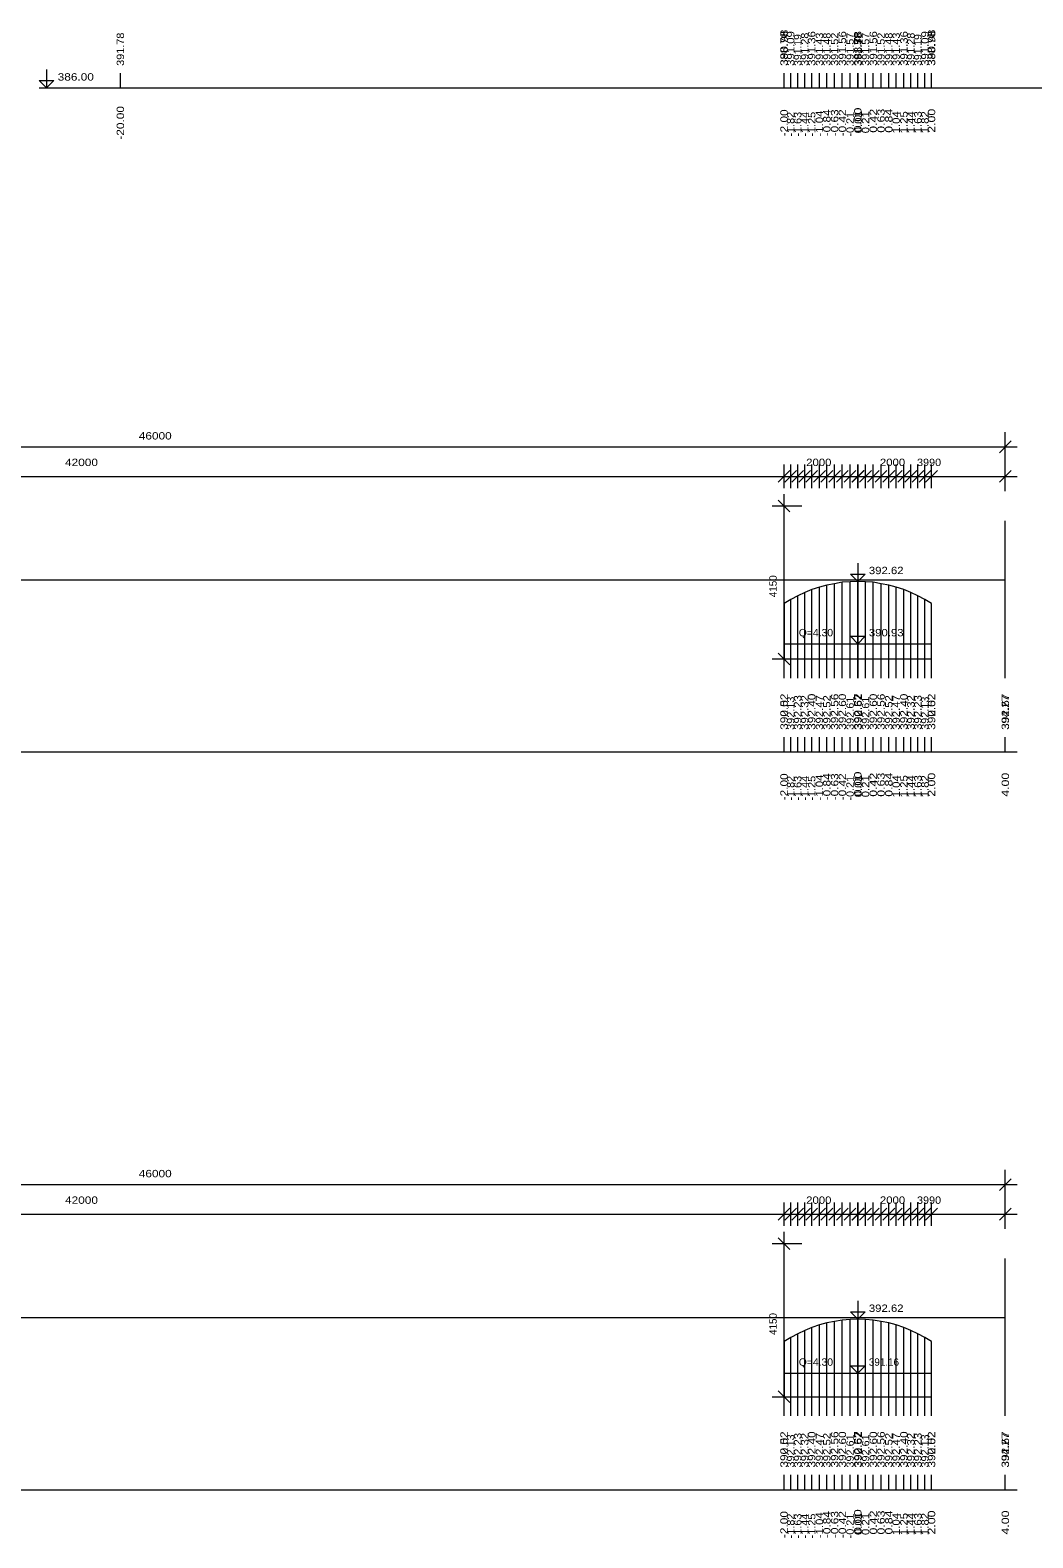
# Model space of a CAD drawing. Extents: x 7 to 442, y -393 to 441.
# Drawn here: x 399.59 to 426.79, y 354.66 to 395.53 of the extents above; entities that cross this region are included whole.
import ezdxf

# ---------------------------------------------------------------- set-up
doc = ezdxf.new("R2010")
doc.units = 0
doc.header["$LTSCALE"] = 0.08
doc.layers.add('7', color=7, linetype='Continuous', lineweight=13)

msp = doc.modelspace()

# ---------------------------------------------------------------- linework, layer by layer
at = {"layer": '7'}
for p, q in [((402.038, 393.966), (402.038, 394.366)), ((420.038, 393.966), (420.038, 394.366)), ((420.038, 393.966), (420.038, 394.366)), ((420.218, 393.966), (420.218, 394.366)), ((420.408, 393.966), (420.408, 394.366)), ((420.598, 393.966), (420.598, 394.366)), ((420.788, 393.966), (420.788, 394.366)), ((420.998, 393.966), (420.998, 394.366)), ((421.198, 393.966), (421.198, 394.366)), ((421.408, 393.966), (421.408, 394.366)), ((421.618, 393.966), (421.618, 394.366)), ((421.828, 393.966), (421.828, 394.366)), ((422.038, 393.966), (422.038, 394.366)), ((422.038, 393.966), (422.038, 394.366)), ((422.038, 393.966), (422.038, 394.366)), ((422.048, 393.966), (422.048, 394.366)), ((422.048, 393.966), (422.048, 394.366)), ((422.248, 393.966), (422.248, 394.366)), ((422.458, 393.966), (422.458, 394.366)), ((422.668, 393.966), (422.668, 394.366)), ((422.878, 393.966), (422.878, 394.366)), ((423.078, 393.966), (423.078, 394.366)), ((423.288, 393.966), (423.288, 394.366)), ((423.478, 393.966), (423.478, 394.366)), ((423.668, 393.966), (423.668, 394.366)), ((423.858, 393.966), (423.858, 394.366)), ((424.038, 393.966), (424.038, 394.366)), ((424.038, 393.966), (424.038, 394.366)), ((399.838, 393.966), (442.358, 393.966)), ((426.038, 383.036), (426.038, 384.636)), ((379.718, 384.236), (426.358, 384.236)), ((425.878, 384.076), (426.198, 384.396)), ((379.718, 383.436), (426.358, 383.436)), ((419.878, 383.276), (420.198, 383.596)), ((419.878, 383.276), (420.198, 383.596)), ((420.038, 383.116), (420.038, 383.756)), ((420.038, 383.116), (420.038, 383.756)), ((420.058, 383.276), (420.378, 383.596)), ((420.218, 383.116), (420.218, 383.756)), ((420.248, 383.276), (420.568, 383.596)), ((420.408, 383.116), (420.408, 383.756)), ((420.438, 383.276), (420.758, 383.596)), ((420.598, 383.116), (420.598, 383.756)), ((420.628, 383.276), (420.948, 383.596)), ((420.788, 383.116), (420.788, 383.756)), ((420.838, 383.276), (421.158, 383.596)), ((420.998, 383.116), (420.998, 383.756)), ((421.038, 383.276), (421.358, 383.596)), ((421.198, 383.116), (421.198, 383.756)), ((421.248, 383.276), (421.568, 383.596)), ((421.408, 383.116), (421.408, 383.756)), ((421.458, 383.276), (421.778, 383.596)), ((421.618, 383.116), (421.618, 383.756)), ((421.668, 383.276), (421.988, 383.596)), ((421.828, 383.116), (421.828, 383.756)), ((421.878, 383.276), (422.198, 383.596)), ((421.878, 383.276), (422.198, 383.596)), ((421.878, 383.276), (422.198, 383.596)), ((421.888, 383.276), (422.208, 383.596)), ((421.888, 383.276), (422.208, 383.596)), ((422.038, 383.116), (422.038, 383.756)), ((422.038, 383.116), (422.038, 383.756)), ((422.038, 383.116), (422.038, 383.756)), ((422.048, 383.116), (422.048, 383.756)), ((422.048, 383.116), (422.048, 383.756)), ((422.088, 383.276), (422.408, 383.596)), ((422.248, 383.116), (422.248, 383.756)), ((422.298, 383.276), (422.618, 383.596)), ((422.458, 383.116), (422.458, 383.756)), ((422.508, 383.276), (422.828, 383.596)), ((422.668, 383.116), (422.668, 383.756)), ((422.718, 383.276), (423.038, 383.596)), ((422.878, 383.116), (422.878, 383.756)), ((422.918, 383.276), (423.238, 383.596)), ((423.078, 383.116), (423.078, 383.756)), ((423.128, 383.276), (423.448, 383.596)), ((423.288, 383.116), (423.288, 383.756)), ((423.318, 383.276), (423.638, 383.596)), ((423.478, 383.116), (423.478, 383.756)), ((423.508, 383.276), (423.828, 383.596)), ((423.668, 383.116), (423.668, 383.756)), ((423.698, 383.276), (424.018, 383.596)), ((423.858, 383.116), (423.858, 383.756)), ((423.878, 383.276), (424.198, 383.596)), ((423.878, 383.276), (424.198, 383.596)), ((424.038, 383.116), (424.038, 383.756)), ((424.038, 383.116), (424.038, 383.756)), ((425.878, 383.276), (426.198, 383.596)), ((425.878, 383.276), (426.198, 383.596)), ((426.038, 383.116), (426.038, 383.756)), ((426.038, 383.116), (426.038, 383.756)), ((419.718, 382.636), (420.518, 382.636)), ((420.198, 382.476), (419.878, 382.796)), ((420.038, 378.326), (420.038, 382.956)), ((426.038, 377.966), (426.038, 382.236)), ((421.618, 377.966), (421.618, 380.566)), ((421.828, 377.966), (421.828, 380.576)), ((422.038, 377.966), (422.038, 380.636)), ((422.038, 377.966), (422.038, 380.586)), ((422.038, 380.586), (422.048, 380.586)), ((422.048, 377.966), (422.048, 380.636)), ((422.048, 377.966), (422.048, 380.586)), ((422.248, 377.966), (422.248, 380.576)), ((422.458, 377.966), (422.458, 380.566)), ((426.038, 377.966), (426.038, 380.636)), ((420.408, 377.966), (420.408, 380.196)), ((420.598, 377.966), (420.598, 380.286)), ((420.788, 377.966), (420.788, 380.366)), ((420.998, 377.966), (420.998, 380.436)), ((421.198, 377.966), (421.198, 380.486)), ((421.408, 377.966), (421.408, 380.526)), ((422.668, 377.966), (422.668, 380.526)), ((422.878, 377.966), (422.878, 380.486)), ((423.078, 377.966), (423.078, 380.436)), ((423.288, 377.966), (423.288, 380.366)), ((423.478, 377.966), (423.478, 380.286)), ((423.668, 377.966), (423.668, 380.196)), ((420.038, 377.966), (420.038, 379.986)), ((420.218, 377.966), (420.218, 380.096)), ((423.858, 377.966), (423.858, 380.096)), ((424.038, 377.966), (424.038, 379.986)), ((420.038, 378.901), (424.038, 378.901)), ((419.718, 378.486), (420.518, 378.486)), ((420.198, 378.326), (419.878, 378.646)), ((420.038, 377.966), (420.038, 378.486)), ((422.038, 377.966), (422.038, 378.486)), ((424.038, 377.966), (424.038, 378.486)), ((420.038, 375.966), (420.038, 376.366)), ((420.038, 375.966), (420.038, 376.366)), ((420.218, 375.966), (420.218, 376.366)), ((420.408, 375.966), (420.408, 376.366)), ((420.598, 375.966), (420.598, 376.366)), ((420.788, 375.966), (420.788, 376.366)), ((420.998, 375.966), (420.998, 376.366)), ((421.198, 375.966), (421.198, 376.366)), ((421.408, 375.966), (421.408, 376.366)), ((421.618, 375.966), (421.618, 376.366)), ((421.828, 375.966), (421.828, 376.366)), ((422.038, 375.966), (422.038, 376.366)), ((422.038, 375.966), (422.038, 376.366)), ((422.038, 375.966), (422.038, 376.366)), ((422.048, 375.966), (422.048, 376.366)), ((422.048, 375.966), (422.048, 376.366)), ((422.248, 375.966), (422.248, 376.366)), ((422.458, 375.966), (422.458, 376.366)), ((422.668, 375.966), (422.668, 376.366)), ((422.878, 375.966), (422.878, 376.366)), ((423.078, 375.966), (423.078, 376.366)), ((423.288, 375.966), (423.288, 376.366)), ((423.478, 375.966), (423.478, 376.366)), ((423.668, 375.966), (423.668, 376.366)), ((423.858, 375.966), (423.858, 376.366)), ((424.038, 375.966), (424.038, 376.366)), ((424.038, 375.966), (424.038, 376.366)), ((426.038, 375.966), (426.038, 376.366)), ((426.038, 375.966), (426.038, 376.366)), ((377.838, 375.966), (426.358, 375.966)), ((426.038, 363.036), (426.038, 364.636)), ((379.718, 364.236), (426.358, 364.236)), ((425.878, 364.076), (426.198, 364.396)), ((379.718, 363.436), (426.358, 363.436)), ((419.878, 363.276), (420.198, 363.596)), ((419.878, 363.276), (420.198, 363.596)), ((420.038, 363.116), (420.038, 363.756)), ((420.038, 363.116), (420.038, 363.756)), ((420.058, 363.276), (420.378, 363.596)), ((420.218, 363.116), (420.218, 363.756)), ((420.248, 363.276), (420.568, 363.596)), ((420.408, 363.116), (420.408, 363.756)), ((420.438, 363.276), (420.758, 363.596)), ((420.598, 363.116), (420.598, 363.756)), ((420.628, 363.276), (420.948, 363.596)), ((420.788, 363.116), (420.788, 363.756)), ((420.838, 363.276), (421.158, 363.596)), ((420.998, 363.116), (420.998, 363.756)), ((421.038, 363.276), (421.358, 363.596)), ((421.198, 363.116), (421.198, 363.756)), ((421.248, 363.276), (421.568, 363.596)), ((421.408, 363.116), (421.408, 363.756)), ((421.458, 363.276), (421.778, 363.596)), ((421.618, 363.116), (421.618, 363.756)), ((421.668, 363.276), (421.988, 363.596)), ((421.828, 363.116), (421.828, 363.756)), ((421.878, 363.276), (422.198, 363.596)), ((421.878, 363.276), (422.198, 363.596)), ((421.878, 363.276), (422.198, 363.596)), ((421.888, 363.276), (422.208, 363.596)), ((421.888, 363.276), (422.208, 363.596)), ((422.038, 363.116), (422.038, 363.756)), ((422.038, 363.116), (422.038, 363.756)), ((422.038, 363.116), (422.038, 363.756)), ((422.048, 363.116), (422.048, 363.756)), ((422.048, 363.116), (422.048, 363.756)), ((422.088, 363.276), (422.408, 363.596)), ((422.248, 363.116), (422.248, 363.756)), ((422.298, 363.276), (422.618, 363.596)), ((422.458, 363.116), (422.458, 363.756)), ((422.508, 363.276), (422.828, 363.596)), ((422.668, 363.116), (422.668, 363.756)), ((422.718, 363.276), (423.038, 363.596)), ((422.878, 363.116), (422.878, 363.756)), ((422.918, 363.276), (423.238, 363.596)), ((423.078, 363.116), (423.078, 363.756)), ((423.128, 363.276), (423.448, 363.596)), ((423.288, 363.116), (423.288, 363.756)), ((423.318, 363.276), (423.638, 363.596)), ((423.478, 363.116), (423.478, 363.756)), ((423.508, 363.276), (423.828, 363.596)), ((423.668, 363.116), (423.668, 363.756)), ((423.698, 363.276), (424.018, 363.596)), ((423.858, 363.116), (423.858, 363.756)), ((423.878, 363.276), (424.198, 363.596)), ((423.878, 363.276), (424.198, 363.596)), ((424.038, 363.116), (424.038, 363.756)), ((424.038, 363.116), (424.038, 363.756)), ((425.878, 363.276), (426.198, 363.596)), ((425.878, 363.276), (426.198, 363.596)), ((426.038, 363.116), (426.038, 363.756)), ((426.038, 363.116), (426.038, 363.756)), ((420.038, 358.326), (420.038, 362.956)), ((419.718, 362.636), (420.518, 362.636)), ((420.198, 362.476), (419.878, 362.796)), ((426.038, 357.966), (426.038, 362.236)), ((421.408, 357.966), (421.408, 360.526)), ((421.618, 357.966), (421.618, 360.566)), ((421.828, 357.966), (421.828, 360.576)), ((422.038, 357.966), (422.038, 360.636)), ((422.038, 357.966), (422.038, 360.586)), ((422.038, 360.586), (422.048, 360.586)), ((422.048, 357.966), (422.048, 360.636)), ((422.048, 357.966), (422.048, 360.586)), ((422.248, 357.966), (422.248, 360.576)), ((422.458, 357.966), (422.458, 360.566)), ((422.668, 357.966), (422.668, 360.526)), ((426.038, 357.966), (426.038, 360.636)), ((420.218, 357.966), (420.218, 360.096)), ((420.408, 357.966), (420.408, 360.196)), ((420.598, 357.966), (420.598, 360.286)), ((420.788, 357.966), (420.788, 360.366)), ((420.998, 357.966), (420.998, 360.436)), ((421.198, 357.966), (421.198, 360.486)), ((422.878, 357.966), (422.878, 360.486)), ((423.078, 357.966), (423.078, 360.436)), ((423.288, 357.966), (423.288, 360.366)), ((423.478, 357.966), (423.478, 360.286)), ((423.668, 357.966), (423.668, 360.196)), ((423.858, 357.966), (423.858, 360.096)), ((420.038, 357.966), (420.038, 359.986)), ((424.038, 357.966), (424.038, 359.986)), ((420.038, 359.126), (424.038, 359.126)), ((419.718, 358.486), (420.518, 358.486)), ((420.198, 358.326), (419.878, 358.646)), ((420.038, 357.966), (420.038, 358.486)), ((422.038, 357.966), (422.038, 358.486)), ((424.038, 357.966), (424.038, 358.486)), ((420.038, 355.966), (420.038, 356.366)), ((420.038, 355.966), (420.038, 356.366)), ((420.218, 355.966), (420.218, 356.366)), ((420.408, 355.966), (420.408, 356.366)), ((420.598, 355.966), (420.598, 356.366)), ((420.788, 355.966), (420.788, 356.366)), ((420.998, 355.966), (420.998, 356.366)), ((421.198, 355.966), (421.198, 356.366)), ((421.408, 355.966), (421.408, 356.366)), ((421.618, 355.966), (421.618, 356.366)), ((421.828, 355.966), (421.828, 356.366)), ((422.038, 355.966), (422.038, 356.366)), ((422.038, 355.966), (422.038, 356.366)), ((422.038, 355.966), (422.038, 356.366)), ((422.048, 355.966), (422.048, 356.366)), ((422.048, 355.966), (422.048, 356.366)), ((422.248, 355.966), (422.248, 356.366)), ((422.458, 355.966), (422.458, 356.366)), ((422.668, 355.966), (422.668, 356.366)), ((422.878, 355.966), (422.878, 356.366)), ((423.078, 355.966), (423.078, 356.366)), ((423.288, 355.966), (423.288, 356.366)), ((423.478, 355.966), (423.478, 356.366)), ((423.668, 355.966), (423.668, 356.366)), ((423.858, 355.966), (423.858, 356.366)), ((424.038, 355.966), (424.038, 356.366)), ((424.038, 355.966), (424.038, 356.366)), ((426.038, 355.966), (426.038, 356.366)), ((426.038, 355.966), (426.038, 356.366)), ((377.838, 355.966), (426.358, 355.966))]:
    msp.add_line(p, q, dxfattribs=at)
for points in [[(400.038, 394.466), (400.038, 393.966), (399.838, 394.166), (400.238, 394.166), (400.038, 393.966)], [(380.038, 380.636), (422.038, 380.636), (422.038, 380.586), (421.828, 380.576), (421.618, 380.566), (421.408, 380.526), (421.198, 380.486), (420.998, 380.436), (420.788, 380.366), (420.598, 380.286), (420.408, 380.196), (420.218, 380.096), (420.038, 379.986), (420.038, 378.486), (422.038, 378.486), (424.038, 378.486), (424.038, 379.986), (423.858, 380.096), (423.668, 380.196), (423.478, 380.286), (423.288, 380.366), (423.078, 380.436), (422.878, 380.486), (422.668, 380.526), (422.458, 380.566), (422.248, 380.576), (422.048, 380.586), (422.048, 380.636), (426.038, 380.636), (426.038, 382.236)], [(422.038, 381.086), (422.038, 380.586), (421.838, 380.786), (422.238, 380.786), (422.038, 380.586)], [(422.038, 379.401), (422.038, 378.901), (421.838, 379.101), (422.238, 379.101), (422.038, 378.901)], [(380.038, 360.636), (422.038, 360.636), (422.038, 360.586), (421.828, 360.576), (421.618, 360.566), (421.408, 360.526), (421.198, 360.486), (420.998, 360.436), (420.788, 360.366), (420.598, 360.286), (420.408, 360.196), (420.218, 360.096), (420.038, 359.986), (420.038, 358.486), (422.038, 358.486), (424.038, 358.486), (424.038, 359.986), (423.858, 360.096), (423.668, 360.196), (423.478, 360.286), (423.288, 360.366), (423.078, 360.436), (422.878, 360.486), (422.668, 360.526), (422.458, 360.566), (422.248, 360.576), (422.048, 360.586), (422.048, 360.636), (426.038, 360.636), (426.038, 362.236)], [(422.038, 361.086), (422.038, 360.586), (421.838, 360.786), (422.238, 360.786), (422.038, 360.586)], [(422.038, 359.626), (422.038, 359.126), (421.838, 359.326), (422.238, 359.326), (422.038, 359.126)]]:
    msp.add_lwpolyline(points, dxfattribs=at)

# ---------------------------------------------------------------- texts
for s, width, p in [('391.78 ', 1.1, (402.138, 394.566)), ('390.98 ', 1.2, (420.138, 394.566)), ('388.78 ', 1.15, (420.138, 394.566)), ('391.09 ', 1.15, (420.318, 394.566)), ('391.19 ', 1.05, (420.508, 394.566)), ('391.28 ', 1.1, (420.698, 394.566)), ('391.36 ', 1.15, (420.888, 394.566)), ('391.43 ', 1.1, (421.098, 394.566)), ('391.48 ', 1.1, (421.298, 394.566)), ('391.52 ', 1.1, (421.508, 394.566)), ('391.56 ', 1.15, (421.718, 394.566)), ('391.57 ', 1.1, (421.928, 394.566)), ('388.78 ', 1.15, (422.138, 394.566)), ('391.78 ', 1.1, (422.138, 394.566)), ('391.58 ', 1.1, (422.138, 394.566)), ('391.58 ', 1.1, (422.148, 394.566)), ('391.78 ', 1.1, (422.148, 394.566)), ('391.57 ', 1.1, (422.348, 394.566)), ('391.56 ', 1.15, (422.558, 394.566)), ('391.52 ', 1.1, (422.768, 394.566)), ('391.48 ', 1.1, (422.978, 394.566)), ('391.43 ', 1.1, (423.178, 394.566)), ('391.36 ', 1.15, (423.388, 394.566)), ('391.28 ', 1.1, (423.578, 394.566)), ('391.19 ', 1.05, (423.768, 394.566)), ('391.09 ', 1.15, (423.958, 394.566)), ('390.98 ', 1.2, (424.138, 394.566)), ('388.78 ', 1.15, (424.138, 394.566)), ('-20.00 ', 1.2, (402.138, 392.566)), (' -2.00 ', 1.2, (420.138, 392.566)), (' -2.00 ', 1.2, (420.138, 392.566)), (' -1.82 ', 1.1, (420.318, 392.566)), (' -1.63 ', 1.1, (420.508, 392.566)), (' -1.44 ', 1.1, (420.698, 392.566)), (' -1.25 ', 1.1, (420.888, 392.566)), (' -1.04 ', 1.15, (421.098, 392.566)), (' -0.84 ', 1.2, (421.298, 392.566)), (' -0.63 ', 1.2, (421.508, 392.566)), (' -0.42 ', 1.2, (421.718, 392.566)), (' -0.21 ', 1.1, (421.928, 392.566)), ('  0.00 ', 1.3, (422.138, 392.566)), ('  0.00 ', 1.3, (422.138, 392.566)), ('  0.00 ', 1.3, (422.138, 392.566)), ('  0.01 ', 1.15, (422.148, 392.566)), ('  0.01 ', 1.15, (422.148, 392.566)), ('  0.21 ', 1.15, (422.348, 392.566)), ('  0.42 ', 1.25, (422.558, 392.566)), ('  0.63 ', 1.25, (422.768, 392.566)), ('  0.84 ', 1.25, (422.978, 392.566)), ('  1.04 ', 1.15, (423.178, 392.566)), ('  1.25 ', 1.15, (423.388, 392.566)), ('  1.44 ', 1.15, (423.578, 392.566)), ('  1.63 ', 1.15, (423.768, 392.566)), ('  1.82 ', 1.15, (423.958, 392.566)), ('  2.00 ', 1.25, (424.138, 392.566)), ('  2.00 ', 1.25, (424.138, 392.566)), ('392.02 ', 1.2, (420.138, 376.566)), ('390.52 ', 1.2, (420.138, 376.566)), ('392.13 ', 1.1, (420.318, 376.566)), ('392.23 ', 1.15, (420.508, 376.566)), ('392.32 ', 1.15, (420.698, 376.566)), ('392.40 ', 1.2, (420.888, 376.566)), ('392.47 ', 1.15, (421.098, 376.566)), ('392.52 ', 1.15, (421.298, 376.566)), ('392.56 ', 1.2, (421.508, 376.566)), ('392.60 ', 1.2, (421.718, 376.566)), ('392.61 ', 1.1, (421.928, 376.566)), ('392.67 ', 1.2, (422.138, 376.566)), ('392.62 ', 1.2, (422.138, 376.566)), ('390.52 ', 1.2, (422.138, 376.566)), ('392.62 ', 1.2, (422.148, 376.566)), ('392.67 ', 1.2, (422.148, 376.566)), ('392.61 ', 1.1, (422.348, 376.566)), ('392.60 ', 1.2, (422.558, 376.566)), ('392.56 ', 1.2, (422.768, 376.566)), ('392.52 ', 1.15, (422.978, 376.566)), ('392.47 ', 1.15, (423.178, 376.566)), ('392.40 ', 1.2, (423.388, 376.566)), ('392.32 ', 1.15, (423.578, 376.566)), ('392.23 ', 1.15, (423.768, 376.566)), ('392.13 ', 1.1, (423.958, 376.566)), ('390.52 ', 1.2, (424.138, 376.566)), ('392.02 ', 1.2, (424.138, 376.566)), ('392.67 ', 1.2, (426.138, 376.566)), ('394.27 ', 1.15, (426.138, 376.566)), (' -2.00 ', 1.2, (420.138, 374.566)), (' -2.00 ', 1.2, (420.138, 374.566)), (' -1.82 ', 1.1, (420.318, 374.566)), (' -1.63 ', 1.1, (420.508, 374.566)), (' -1.44 ', 1.1, (420.698, 374.566)), (' -1.25 ', 1.1, (420.888, 374.566)), (' -1.04 ', 1.15, (421.098, 374.566)), (' -0.84 ', 1.2, (421.298, 374.566)), (' -0.63 ', 1.2, (421.508, 374.566)), (' -0.42 ', 1.2, (421.718, 374.566)), (' -0.21 ', 1.1, (421.928, 374.566)), ('  0.00 ', 1.3, (422.138, 374.566)), ('  0.00 ', 1.3, (422.138, 374.566)), ('  0.00 ', 1.3, (422.138, 374.566)), ('  0.01 ', 1.15, (422.148, 374.566)), ('  0.01 ', 1.15, (422.148, 374.566)), ('  0.21 ', 1.15, (422.348, 374.566)), ('  0.42 ', 1.25, (422.558, 374.566)), ('  0.63 ', 1.25, (422.768, 374.566)), ('  0.84 ', 1.25, (422.978, 374.566)), ('  1.04 ', 1.15, (423.178, 374.566)), ('  1.25 ', 1.15, (423.388, 374.566)), ('  1.44 ', 1.15, (423.578, 374.566)), ('  1.63 ', 1.15, (423.768, 374.566)), ('  1.82 ', 1.15, (423.958, 374.566)), ('  2.00 ', 1.25, (424.138, 374.566)), ('  2.00 ', 1.25, (424.138, 374.566)), ('  4.00 ', 1.25, (426.138, 374.566)), ('  4.00 ', 1.25, (426.138, 374.566)), ('392.02 ', 1.2, (420.138, 356.566)), ('390.52 ', 1.2, (420.138, 356.566)), ('392.13 ', 1.1, (420.318, 356.566)), ('392.23 ', 1.15, (420.508, 356.566)), ('392.32 ', 1.15, (420.698, 356.566)), ('392.40 ', 1.2, (420.888, 356.566)), ('392.47 ', 1.15, (421.098, 356.566)), ('392.52 ', 1.15, (421.298, 356.566)), ('392.56 ', 1.2, (421.508, 356.566)), ('392.60 ', 1.2, (421.718, 356.566)), ('392.61 ', 1.1, (421.928, 356.566)), ('392.67 ', 1.2, (422.138, 356.566)), ('392.62 ', 1.2, (422.138, 356.566)), ('390.52 ', 1.2, (422.138, 356.566)), ('392.62 ', 1.2, (422.148, 356.566)), ('392.67 ', 1.2, (422.148, 356.566)), ('392.61 ', 1.1, (422.348, 356.566)), ('392.60 ', 1.2, (422.558, 356.566)), ('392.56 ', 1.2, (422.768, 356.566)), ('392.52 ', 1.15, (422.978, 356.566)), ('392.47 ', 1.15, (423.178, 356.566)), ('392.40 ', 1.2, (423.388, 356.566)), ('392.32 ', 1.15, (423.578, 356.566)), ('392.23 ', 1.15, (423.768, 356.566)), ('392.13 ', 1.1, (423.958, 356.566)), ('390.52 ', 1.2, (424.138, 356.566)), ('392.02 ', 1.2, (424.138, 356.566)), ('392.67 ', 1.2, (426.138, 356.566)), ('394.27 ', 1.15, (426.138, 356.566)), (' -2.00 ', 1.2, (420.138, 354.566)), (' -2.00 ', 1.2, (420.138, 354.566)), (' -1.82 ', 1.1, (420.318, 354.566)), (' -1.63 ', 1.1, (420.508, 354.566)), (' -1.44 ', 1.1, (420.698, 354.566)), (' -1.25 ', 1.1, (420.888, 354.566)), (' -1.04 ', 1.15, (421.098, 354.566)), (' -0.84 ', 1.2, (421.298, 354.566)), (' -0.63 ', 1.2, (421.508, 354.566)), (' -0.42 ', 1.2, (421.718, 354.566)), (' -0.21 ', 1.1, (421.928, 354.566)), ('  0.00 ', 1.3, (422.138, 354.566)), ('  0.00 ', 1.3, (422.138, 354.566)), ('  0.00 ', 1.3, (422.138, 354.566)), ('  0.01 ', 1.15, (422.148, 354.566)), ('  0.01 ', 1.15, (422.148, 354.566)), ('  0.21 ', 1.15, (422.348, 354.566)), ('  0.42 ', 1.25, (422.558, 354.566)), ('  0.63 ', 1.25, (422.768, 354.566)), ('  0.84 ', 1.25, (422.978, 354.566)), ('  1.04 ', 1.15, (423.178, 354.566)), ('  1.25 ', 1.15, (423.388, 354.566)), ('  1.44 ', 1.15, (423.578, 354.566)), ('  1.63 ', 1.15, (423.768, 354.566)), ('  1.82 ', 1.15, (423.958, 354.566)), ('  2.00 ', 1.25, (424.138, 354.566)), ('  2.00 ', 1.25, (424.138, 354.566)), ('  4.00 ', 1.25, (426.138, 354.566)), ('  4.00 ', 1.25, (426.138, 354.566))]:
    msp.add_text(s, height=0.2, rotation=90, dxfattribs=dict(at, width=width)).set_placement(p)
for s, width, p in [('386.00', 1.2, (400.338, 394.166)), ('46000', 1.2, (402.538, 384.436)), ('42000', 1.2, (400.538, 383.716)), ('2000', 1.15, (420.638, 383.716)), ('2000', 1.15, (422.638, 383.716)), ('3990', 1.1, (423.643, 383.716)), ('392.62', 1.15, (422.338, 380.786)), ('Q=4.30', 1.05, (420.438, 379.101)), ('390.93', 1.15, (422.338, 379.101)), ('46000', 1.2, (402.538, 364.436)), ('42000', 1.2, (400.538, 363.716)), ('2000', 1.15, (420.638, 363.716)), ('2000', 1.15, (422.638, 363.716)), ('3990', 1.1, (423.643, 363.716)), ('392.62', 1.15, (422.338, 360.786)), ('Q=4.30', 1.05, (420.438, 359.326))]:
    msp.add_text(s, height=0.2, dxfattribs=dict(at, width=width)).set_placement(p)
for p in [(419.838, 380.161), (419.838, 360.161)]:
    msp.add_text('4150', height=0.2, rotation=90, dxfattribs=at).set_placement(p)
msp.add_text('391.16', height=0.2, dxfattribs=at).set_placement((422.338, 359.326))

doc.saveas('drawing.dxf')
